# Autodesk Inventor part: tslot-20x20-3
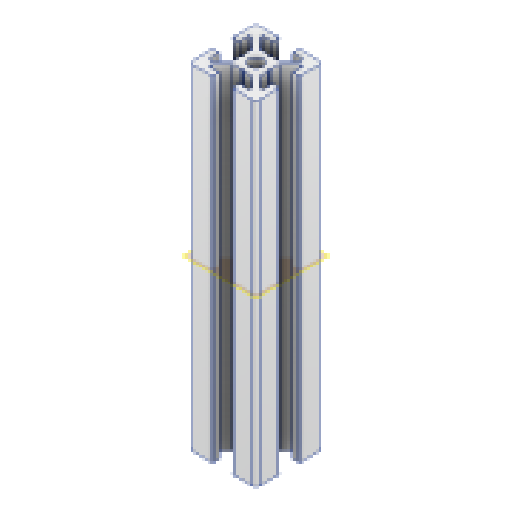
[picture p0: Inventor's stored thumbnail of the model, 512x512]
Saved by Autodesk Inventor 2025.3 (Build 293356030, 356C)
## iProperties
Created: 2025-03
Part Number: tslot-20x20-3
Material: Alluminio 6061
Document SubType Name: Modeling
Designer: Ryzen5700u
Density: 2.7 g/cm^3
Appearance: Alluminio - Piatto
Author: Ryzen5700u
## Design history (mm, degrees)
feature "Base1"
sketch "Schizzo1"
  geometry: L1 (3.761, -16)-(4.7, -16) reference; L2 (3.761, -16)-(0.7, -12.939) reference; L3 (0.7, -12.939)-(0.7, -10.52) reference; L4 (0.4, -10)-(0.7, -10.52) reference; L5 (0.4, -10)-(0.7, -9.48) reference; L6 (0.7, -7.061)-(0.7, -9.48) reference; L7 (3.761, -4)-(0.7, -7.061) reference; L8 (3.761, -4)-(4.7, -4) reference; L9 (4.7, -4)-(4.7, -7) reference; L10 (4.7, -7)-(6.4, -7) reference; L11 (6.7, -6.7)-(6.7, -1) reference; L12 (5.7, 0)-(0, 0) reference; L13 (-0.3, -2)-(-0.3, -0.3) reference; L14 (2.7, -2)-(-0.3, -2) reference; L15 (2.7, -2.939)-(2.7, -2) reference; L16 (2.7, -2.939)-(-0.361, -6) reference; L17 (-0.361, -6)-(-2.78, -6) reference; L18 (-3.3, -6.3)-(-2.78, -6) reference; L19 (-3.3, -6.3)-(-3.82, -6) reference; L20 (-6.239, -6)-(-3.82, -6) reference; L21 (-9.3, -2.939)-(-6.239, -6) reference; L22 (-9.3, -2.939)-(-9.3, -2) reference; L23 (-9.3, -2)-(-6.3, -2) reference; L24 (-6.3, -2)-(-6.3, -0.3) reference; L25 (-12.3, 0)-(-6.6, 0) reference; L26 (-13.3, -6.7)-(-13.3, -1) reference; L27 (-11.3, -7)-(-13, -7) reference; L28 (-11.3, -4)-(-11.3, -7) reference; L29 (-10.361, -4)-(-11.3, -4) reference; L30 (-10.361, -4)-(-7.3, -7.061) reference; L31 (-7.3, -7.061)-(-7.3, -9.48) reference; L32 (-7, -10)-(-7.3, -9.48) reference; L33 (-7, -10)-(-7.3, -10.52) reference; L34 (-7.3, -12.939)-(-7.3, -10.52) reference; L35 (-10.361, -16)-(-7.3, -12.939) reference; L36 (-10.361, -16)-(-11.3, -16) reference; L37 (-11.3, -16)-(-11.3, -13) reference; L38 (-11.3, -13)-(-13, -13) reference; L39 (-13.3, -13.3)-(-13.3, -19) reference; L40 (-12.3, -20)-(-6.6, -20) reference; L41 (-6.3, -18)-(-6.3, -19.7) reference; L42 (-9.3, -18)-(-6.3, -18) reference; L43 (-9.3, -17.061)-(-9.3, -18) reference; L44 (-9.3, -17.061)-(-6.239, -14) reference; L45 (-6.239, -14)-(-3.82, -14) reference; L46 (-3.3, -13.7)-(-3.82, -14) reference; L47 (-3.3, -13.7)-(-2.78, -14) reference; L48 (-0.361, -14)-(-2.78, -14) reference; L49 (2.7, -17.061)-(-0.361, -14) reference; L50 (2.7, -17.061)-(2.7, -18) reference; L51 (2.7, -18)-(-0.3, -18) reference; L52 (-0.3, -18)-(-0.3, -19.7) reference; L53 (5.7, -20)-(0, -20) reference; L54 (6.7, -13.3)-(6.7, -19) reference; L55 (4.7, -13)-(6.4, -13) reference; L56 (4.7, -16)-(4.7, -13) reference; C1 r 2.1 at (-3.3, -10) reference; A1 r 0.3 centre (6.4, -6.7) between (6.4, -7) and (6.7, -6.7) reference; A2 r 1 centre (5.7, -1) between (6.7, -1) and (5.7, 0) reference; A3 r 0.3 centre (0, -0.3) between (0, 0) and (-0.3, -0.3) reference; A4 r 0.3 centre (-6.6, -0.3) between (-6.3, -0.3) and (-6.6, 0) reference; A5 r 1 centre (-12.3, -1) between (-12.3, 0) and (-13.3, -1) reference; A6 r 0.3 centre (-13, -6.7) between (-13.3, -6.7) and (-13, -7) reference; A7 r 0.3 centre (-13, -13.3) between (-13, -13) and (-13.3, -13.3) reference; A8 r 1 centre (-12.3, -19) between (-13.3, -19) and (-12.3, -20) reference; A9 r 0.3 centre (-6.6, -19.7) between (-6.6, -20) and (-6.3, -19.7) reference; A10 r 0.3 centre (0, -19.7) between (-0.3, -19.7) and (0, -20) reference; A11 r 1 centre (5.7, -19) between (5.7, -20) and (6.7, -19) reference; A12 r 0.3 centre (6.4, -13.3) between (6.7, -13.3) and (6.4, -13) reference; 1 further point
extrude "Estrusione1" join sketch "Schizzo1" distance "d0" = 90; taper "d1" = 0 deg
node "Piano di lavoro1"
node "Solido1"
node "Linea chiusa proiettata1"
